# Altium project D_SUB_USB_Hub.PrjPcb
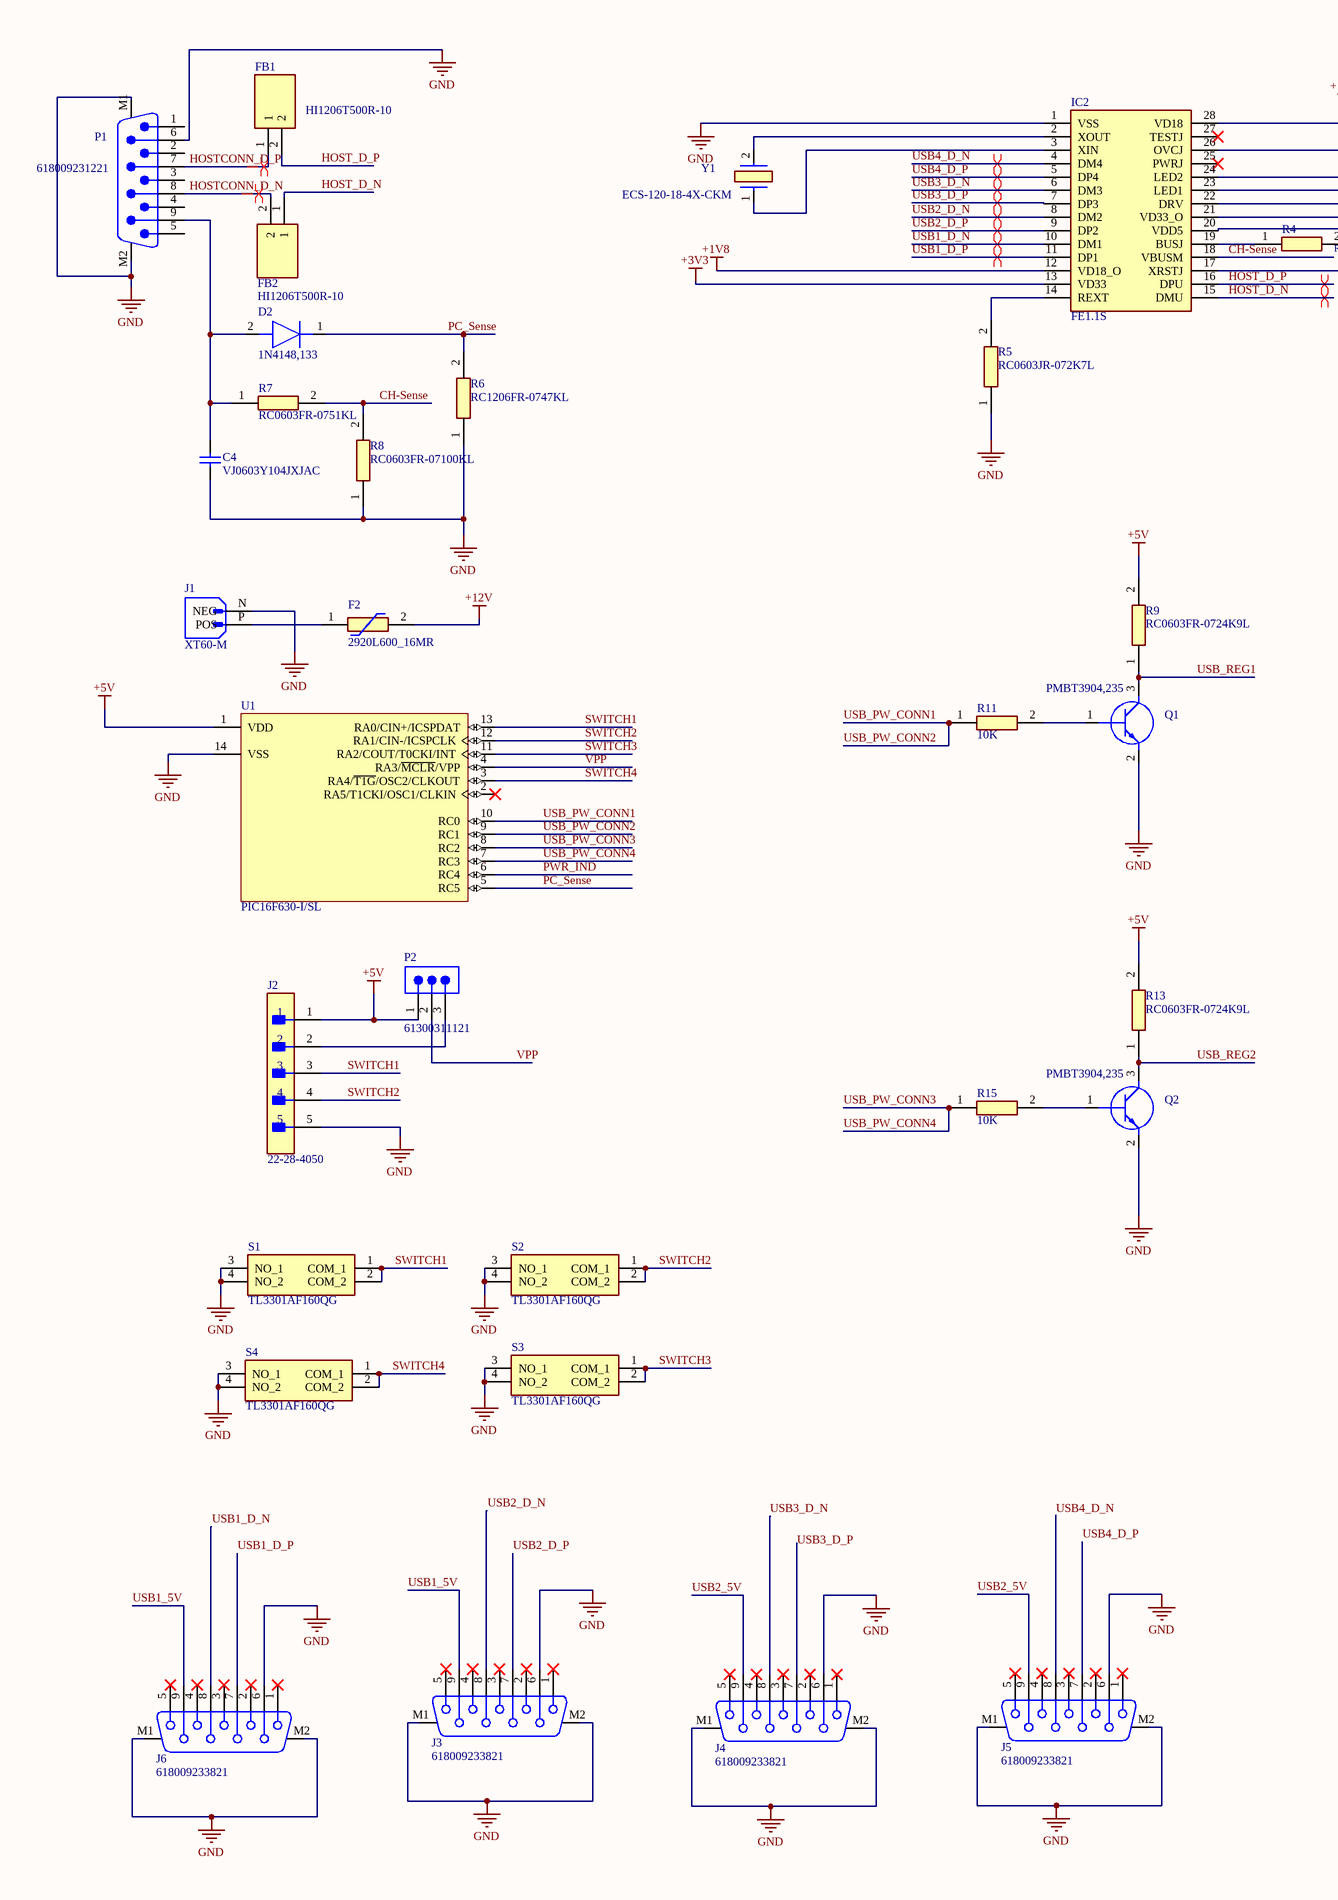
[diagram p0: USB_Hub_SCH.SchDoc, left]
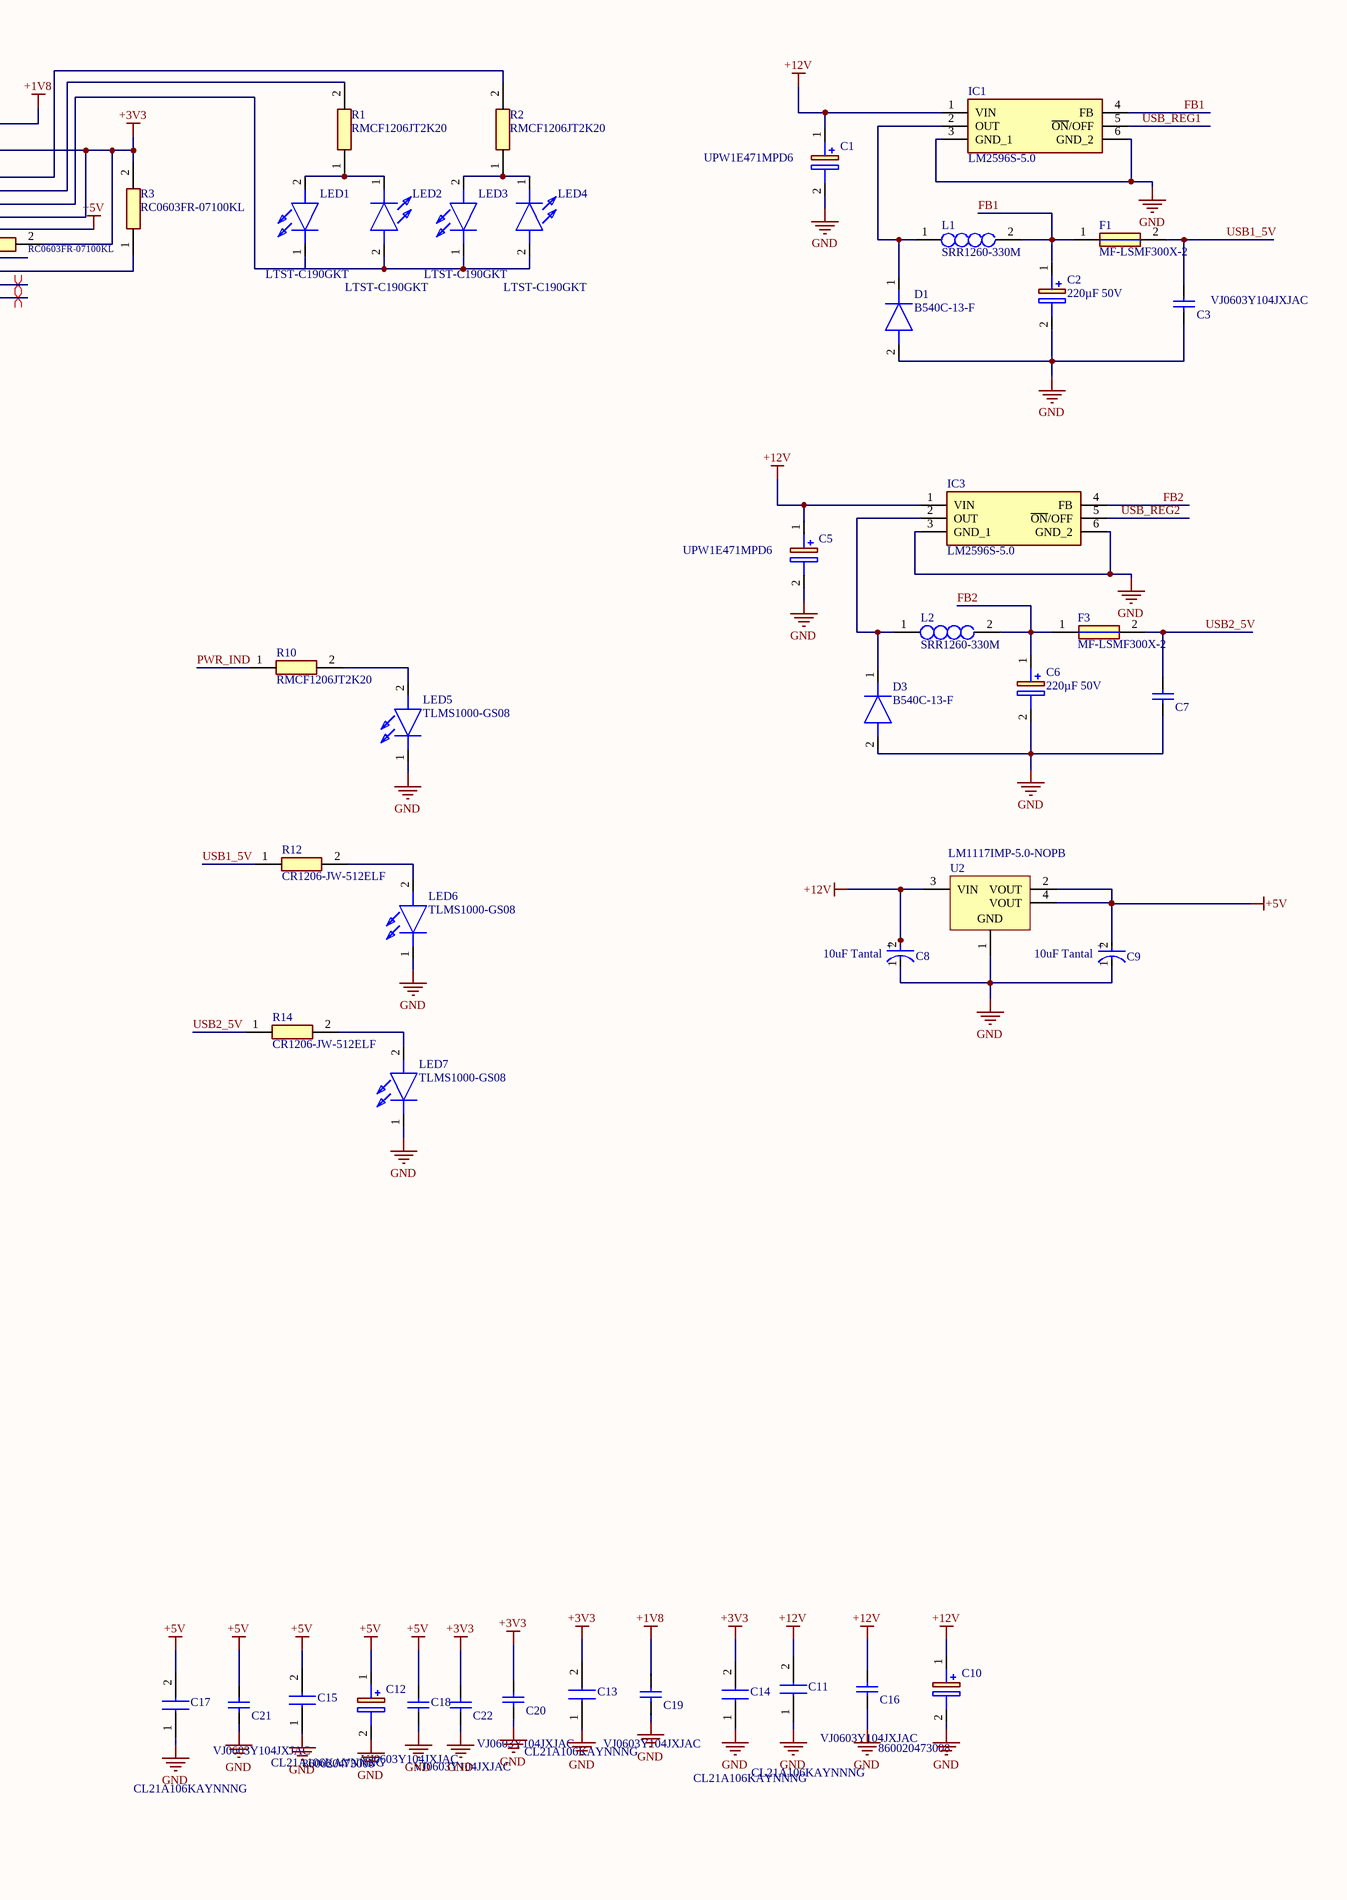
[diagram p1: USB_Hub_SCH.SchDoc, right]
1 sheet, 74 parts. Net scope: global (net labels, ports and power ports of the same name join across sheets).
Board file: USB_Hub_PCB.PcbDoc

## Sheet USB_Hub_SCH.SchDoc
size 500 x 400 mm; SheetNumber: 1; SheetTotal: 1

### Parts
C1  UPW1E471MPD6  [CAPPRD350W60D825H2200]
C2  220µF 50V  [EEEFK1V331P]
C3  VJ0603Y104JXJAC  [CAPC1608X92X38LL15T08]
C4  VJ0603Y104JXJAC  [CAPC1608X92X38LL15T08]
C5  UPW1E471MPD6  [CAPPRD350W60D825H2200]
C6  220µF 50V  [EEEFK1V331P]
C7  VJ0603Y104JXJAC  [CAPC1608X92X38LL15T08]  (value not drawn)
C8  10uF Tantal  [FP-T491D-MFG]
C9  10uF Tantal  [FP-T491D-MFG]
C10  860020473008  [CAPPRD250W52D630H1250]
C11  CL21A106KAYNNNG  [CAPC2012X145N]
C12  860020473008  [CAPPRD250W52D630H1250]
C13  CL21A106KAYNNNG  [CAPC2012X145N]
C14  CL21A106KAYNNNG  [CAPC2012X145N]
C15  CL21A106KAYNNNG  [CAPC2012X145N]
C16  VJ0603Y104JXJAC  [CAPC1608X92X38LL15T08]
C17  CL21A106KAYNNNG  [CAPC2012X145N]
C18  VJ0603Y104JXJAC  [CAPC1608X92X38LL15T08]
C19  VJ0603Y104JXJAC  [CAPC1608X92X38LL15T08]
C20  VJ0603Y104JXJAC  [CAPC1608X92X38LL15T08]
C21  VJ0603Y104JXJAC  [CAPC1608X92X38LL15T08]
C22  VJ0603Y104JXJAC  [CAPC1608X92X38LL15T08]
D1  B540C-13-F  [DIOM7959X250N]
D2  1N4148,133  [DIOAD1165W56L425D185]
D3  B540C-13-F  [DIOM7959X250N]
F1  MF-LSMF300X-2  [FUSC7451X85N]
F2  2920L600_16MR  [FUSC7451X160N]
F3  MF-LSMF300X-2  [FUSC7451X85N]
FB1  HI1206T500R-10  [BEADC3216X130N]
FB2  HI1206T500R-10  [BEADC3216X130N]
IC1  LM2596S-5.0  [KTT0005B]
IC2  FE1.1S  [SOP64P600X175-28N]
IC3  LM2596S-5.0  [KTT0005B]
J1  XT60-M  [XT60-M-Footprint-1]
J2  22-28-4050  [FP-22-28-4050-MFG]
J3  618009233821  [618009233821]
J4  618009233821  [618009233821]
J5  618009233821  [618009233821]
J6  618009233821  [618009233821]
L1  SRR1260-330M  [SRR1260-150M]
L2  SRR1260-330M  [SRR1260-150M]
LED1  LTST-C190GKT  [LEDC1608X90N]
LED2  LTST-C190GKT  [LEDC1608X90N]
LED3  LTST-C190GKT  [LEDC1608X90N]
LED4  LTST-C190GKT  [LEDC1608X90N]
LED5  TLMS1000-GS08  [LEDC1608X65N]
LED6  TLMS1000-GS08  [LEDC1608X65N]
LED7  TLMS1000-GS08  [LEDC1608X65N]
P1  618009231221  [618009231221]
P2  61300311121  [61300311121]
Q1  PMBT3904,235  [SOT95P230X110-3N]
Q2  PMBT3904,235  [SOT95P230X110-3N]
R1  RMCF1206JT2K20  [RESC3216X70N]
R2  RMCF1206JT2K20  [RESC3216X70N]
R3  RC0603FR-07100KL  [RESC1608X55N]
R4  RC0603FR-07100KL  [RESC1608X55N]
R5  RC0603JR-072K7L  [RESC1608X55N]
R6  RC1206FR-0747KL  [RESC3116X65N]
R7  RC0603FR-0751KL  [RESC1608X55N]
R8  RC0603FR-07100KL  [RESC1608X55N]
R9  RC0603FR-0724K9L  [RESC1608X55N]
R10  RMCF1206JT2K20  [RESC3216X70N]
R11  10K  [RESC1608X55N]
R12  CR1206-JW-512ELF  [RESC3216X70N]
R13  RC0603FR-0724K9L  [RESC1608X55N]
R14  CR1206-JW-512ELF  [RESC3216X70N]
R15  10K  [RESC1608X55N]
S1  TL3301AF160QG  [TL3301AF160QG]
S2  TL3301AF160QG  [TL3301AF160QG]
S3  TL3301AF160QG  [TL3301AF160QG]
S4  TL3301AF160QG  [TL3301AF160QG]
U1  PIC16F630-I/SL  [SOIC-SL14_L]
U2  LM1117IMP-5.0-NOPB  [DCY0004A_M]
Y1  ECS-120-18-4X-CKM  [ECS120184XCKM]

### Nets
+1V8: C19.2 IC2.12(VD18_O) IC2.28(VD18)
+3V3: C13.2 C14.2 C20.2 C22.2 IC2.13(VD33) IC2.21(VD33_O) IC2.26(OVCJ) R3.2 R4.2
+5V: C9.2(A) C12.1(+) C15.2 C17.2 C18.2 C21.2 IC2.20(VDD5) J2.1 P2.1 R9.2 R13.2 U1.1(VDD) U2.2(VOUT) U2.4(VOUT)
+12V: C1.1(+) C5.1(+) C8.2(A) C10.1(+) C11.2 C16.2 F2.2 IC1.1(VIN) IC3.1(VIN) U2.3(VIN)
GND: C1.2(-) C2.2(-) C3.1 C4.1 C5.2(-) C6.2(-) C7.1 C8.1(C) C9.1(C) C10.2(-) C11.1 C12.2(-) C13.1 C14.1 C15.1 C16.1 C17.1 C18.1 C19.1 C20.1 C21.1 C22.1 D1.2(A) D3.2(A) IC1.3(GND_1) IC1.6(GND_2) IC2.1(VSS) IC3.3(GND_1) IC3.6(GND_2) J1.N(NEG) J2.5 J3.6 J3.M1 J3.M2 J4.6 J4.M1 J4.M2 J5.6 J5.M1 J5.M2 J6.6 J6.M1 J6.M2 LED5.1(K) LED6.1(K) LED7.1(K) P1.6 P1.M1 P1.M2 Q1.2(E) Q2.2(E) R5.1 R6.1 R8.1 S1.3(NO_1) S1.4(NO_2) S2.3(NO_1) S2.4(NO_2) S3.3(NO_1) S3.4(NO_2) S4.3(NO_1) S4.4(NO_2) U1.14(VSS) U2.1(GND)
CH-Sense: IC2.18(VBUSM) R7.2 R8.2
FB1: C2.1(+) F1.1 IC1.4(FB) L1.2
FB2: C6.1(+) F3.1 IC3.4(FB) L2.2
HOST_D_N: FB2.1 IC2.15(DMU)
HOST_D_P: FB1.2 IC2.16(DPU)
HOSTCONN_D_N: FB2.2 P1.8
HOSTCONN_D_P: FB1.1 P1.7
PC_Sense: D2.1(K) R6.2 U1.5(RC5)
PWR_IND: R10.1 U1.6(RC4)
SWITCH1: J2.3 S1.1(COM_1) S1.2(COM_2) U1.13(RA0/CIN+/ICSPDAT)
SWITCH2: J2.4 S2.1(COM_1) S2.2(COM_2) U1.12(RA1/CIN-/ICSPCLK)
SWITCH3: S3.1(COM_1) S3.2(COM_2) U1.11(RA2/COUT/T0CKI/INT)
SWITCH4: S4.1(COM_1) S4.2(COM_2) U1.3(RA4/~{T1G}/OSC2/CLKOUT)
USB1_5V: C3.2 F1.2 J3.9 J6.9 R12.1
USB1_D_N: IC2.10(DM1) J6.8
USB1_D_P: IC2.11(DP1) J6.7
USB2_5V: C7.2 F3.2 J4.9 J5.9 R14.1
USB2_D_N: IC2.8(DM2) J3.8
USB2_D_P: IC2.9(DP2) J3.7
USB3_D_N: IC2.6(DM3) J4.8
USB3_D_P: IC2.7(DP3) J4.7
USB4_D_N: IC2.4(DM4) J5.8
USB4_D_P: IC2.5(DP4) J5.7
USB_PW_CONN1: R11.1 U1.9(RC1) U1.10(RC0)  [also labelled USB_PW_CONN2]
USB_PW_CONN3: R15.1 U1.7(RC3) U1.8(RC2)  [also labelled USB_PW_CONN4]
USB_REG1: IC1.5(~{ON}/OFF) Q1.3(C) R9.1
USB_REG2: IC3.5(~{ON}/OFF) Q2.3(C) R13.1
VPP: P2.2 U1.4(RA3/~{MCLR}/VPP)
NetC4_2: C4.2 D2.2(A) P1.9 R7.1
NetD1_1: D1.1(K) IC1.2(OUT) L1.1
NetD3_1: D3.1(K) IC3.2(OUT) L2.1
NetF2_1: F2.1 J1.P(POS)
NetIC2_2: IC2.2(XOUT) Y1.2(CRYSTAL_2)
NetIC2_3: IC2.3(XIN) Y1.1
NetIC2_14: IC2.14(REXT) R5.2
NetIC2_17: IC2.17(XRSTJ) R3.1
NetIC2_19: IC2.19(BUSJ) R4.1
NetIC2_22: IC2.22(DRV) LED1.1(K) LED2.2(A) LED3.1(K) LED4.2(A)
NetIC2_23: IC2.23(LED1) R1.2
NetIC2_24: IC2.24(LED2) R2.2
NetJ2_2: J2.2 P2.3
NetLED1_2: LED1.2(A) LED2.1(K) R1.1
NetLED3_2: LED3.2(A) LED4.1(K) R2.1
NetLED5_2: LED5.2(A) R10.2
NetLED6_2: LED6.2(A) R12.2
NetLED7_2: LED7.2(A) R14.2
NetQ1_1: Q1.1(B) R11.2
NetQ2_1: Q2.1(B) R15.2

Not connected (* = marked no-connect by the designer): IC2 25(PWRJ)* 27(TESTJ)*; J3 1* 2* 3* 4* 5*; J4 1* 2* 3* 4* 5*; J5 1* 2* 3* 4* 5*; J6 1* 2* 3* 4* 5*; P1 1 2 3 4 5; U1 2(RA5/T1CKI/OSC1/CLKIN)*

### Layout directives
differential pair: HOST_D_N, HOST_D_P, HOSTCONN_D_N, HOSTCONN_D_P, USB1_D_N, USB1_D_P, USB2_D_N, USB2_D_P, USB3_D_N, USB3_D_P, USB4_D_N, USB4_D_P

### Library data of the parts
C1 C5 = UPW1E471MPD6: Capacitor Polarised; Manufacturer_Name: Nichicon
C2 C6 = EEE-1HA221P: Capacitor Polarised / EEE-1HA221P; Manufacturer_Name: Panasonic
C3 C4 C7 C16 C18-C22 = CMP-001-00083-1: Cap Ceramic 0.1uF 16V X7R 5% SMD 0603 150°C Paper T/R
C8 C9 = CMP-001-00086-1: Cap Tant Solid 10uF 25V D CASE 10% (7.3 X 4.3 X 2.8mm) Inward L SMD 7343-31 1 Ohm 125C T/R / T491D106K025AT
C10 C12 = 860020473008: Capacitor Polarised; Manufacturer_Name: Wurth Elektronik
C11 C13-C15 C17 = CL21A106KAYNNNG: Capacitor; Manufacturer_Name: SAMSUNG
D1 D3 = B540C-13-F: Diode; Manufacturer_Name: Diodes Incorporated
D2 = 1N4148,133: Diode; Manufacturer_Name: Nexperia
F1 F3 = MF-LSMF300X-2: Fuse; Manufacturer_Name: Bourns
F2 = 2920L600_16MR: Resettable Fuse; Manufacturer_Name: LITTELFUSE; Manufacturer_Part_Number: 2920L600/16MR
FB1 FB2 = HI1206T500R-10: Ferrite Bead; Manufacturer_Name: Laird Technologies
IC1 IC3 = LM2596S-5.0: Integrated Circuit; Manufacturer_Name: Texas Instruments
IC2 = FE1.1S: Integrated Circuit; Manufacturer_Name: JFD IC
J1 = CMP-002-00074-2: XT60 Male Connector
J2 = CMP-00257-00278173-1: 22-28-4050 KK® 254 Breakaway Header, Vertical, 5 Circuits, Tin (Sn) Plating, Mating Pin Length 6.09mm; NexarPartId: 278173; Voltage Rating: 250V; Number of Contacts: 5; Contact Resistance: 20mΩ; Gender: Male; Pitch: 2.54mm; Connector Type: Male Pin; Current Rating: 4A; Glow Wire Compliant: Non-compliant; Max Voltage Rating (DC): 250.25kV
J3-J6 = CMP-03913-89205522-1: 618009233821 D-Sub, 10.30mm Female Angled PCB Connector without Hex Screw, 9 pins; Pitch: 2.77mm; Contact Resistance: 30mΩ; Current Rating: 3A; Insulation Resistance: 5GΩ; Operating Supply Voltage: 125V
L1 L2 = SRR1260-330M: Inductor; Manufacturer_Name: Bourns
LED1-LED4 = LTST-C190GKT: LED; Manufacturer_Name: Lite-On
LED5-LED7 = TLMS1000-GS08: LED; Manufacturer_Name: Vishay
P1 = CMP-1502-00284-2: NexarPartId: 22865742; Pitch: 2.77mm; Number of Contacts: 9; Operating Supply Voltage: 125V; Insulation Resistance: 5GΩ; Gender: Male; Contact Resistance: 30mΩ; Current Rating: 3A
P2 = CMP-1502-01062-3: NexarPartId: 32855521; Current Rating: 3A; Voltage Rating: 250V; Number of Positions: 3; Pitch: 2.54mm; Contact Resistance: 20mΩ; Connector Type: Male Pin; Gender: Male
Q1 Q2 = PMBT3904,235: Transistor BJT NPN; Manufacturer_Name: Nexperia
R1 R2 = RMCF1206JT2K20: Resistor; Manufacturer_Name: Stackpole Electronics
R3 R4 R8 = RC0603FR-07100KL: Resistor; Manufacturer_Name: YAGEO
R5 = RC0603JR-072K7L: Resistor; Manufacturer_Name: KEMET
R6 = RC1206FR-0747KL: Resistor; Manufacturer_Name: YAGEO
R7 = RC0603FR-0751KL: Resistor; Manufacturer_Name: KEMET
R9 R13 = RC0603FR-0724K9L: Resistor; Manufacturer_Name: YAGEO
R10 R12 = RMCF1206JT2K20: Resistor 5.1K 1206; Manufacturer_Name: Stackpole Electronics
R11 R15 = RC0603FR0710KL: Manufacturer_Name: KEMET
R14 = RMCF1206JT2K20: Resistor  5.1K 1206; Manufacturer_Name: Stackpole Electronics
S1-S4 = TL3301AF160QG: Switch; Manufacturer_Name: E-Switch
U1 = CMP-0115-01006-1: FLASH-Based 8-Bit CMOS Microcontroller, 1K (x14-Bit words) FLASH, 64 Bytes SRAM, 14-Pin SOIC, 2.0 to 5.5V Supply Range, Industrial Temperature
U2 = CMP-019-00021-3: Low-Dropout Linear Regulator, 800 mA, -40 to 125 degC, 4-Pin SOT-223 (DCY), Green (RoHS & no Sb/Br), Tape and Reel; Manufacturer: Texas Instruments; Dropout Voltage: 1.2V; Nominal Output Voltage: 5V; Max Ouput Current: 800mA; Outputs: 1; Min Input Voltage: 2.6V; Max Input Voltage: 15V
Y1 = ECS-120-18-4X-CKM: Crystal or Oscillator; Manufacturer_Name: ECS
